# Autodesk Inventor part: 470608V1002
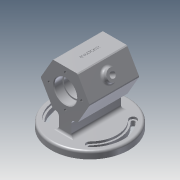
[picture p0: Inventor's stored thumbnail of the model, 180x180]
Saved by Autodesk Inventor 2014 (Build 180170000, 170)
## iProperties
Created: 2017-06
Part Number: 470608V1002
Material: 알루미늄 6061
Document SubType Name: Modeling
Designer: user
Density: 2.71 g/cm^3
Appearance: 알루미늄 - 평지
Author: user
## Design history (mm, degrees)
sketch "스케치1"
  geometry: C1 r 55 at (0, 0); 1 further point
  constraints: 1 centre point, 1 coincident
  dimensions: "d0" = 110 diameter of C1
extrude "돌출1" new body sketch "스케치1" stored distance "d1" = 10; taper "d2" = 0 deg
sketch "스케치2"
  geometry: C1 r 55 at (0, 0) reference
sketch "스케치4" dims "d4" = 60, "d10" = 46
  geometry: L1 (17.321, 87)-(34.641, 57); L2 (34.641, 57)-(17.321, 27); L3 (17.321, 27)-(-17.321, 27); L4 (-17.321, 27)-(-34.641, 57); L5 (-34.641, 57)-(-17.321, 87); L6 (-17.321, 87)-(17.321, 87); L7 (-55, -5)-(55, -5) reference; L8 (0, 110.989)-(0, -17.076); L9 (-38.809, 57)-(46.568, 57); C1 r 16 at (0, 57); 9 further points
  constraints: 16 end point, 3 coincident, 3 vertical alignment, 2 perpendicular, 1 centre point, 1 midpoint, 1 point on line, 22 other
  dimensions: "d5" = 62 distance from line of point (0, 57) L7; "d6" = 92 distance from line of L7 point (0, 87); "d11" = 32 diameter of C1; "d16" = 360 deg dimension on point (0, 57) point (0, 80) (derived)
extrude "돌출2" join sketch "스케치4" stored distance "d7" = 70; taper "d8" = 0 deg
sketch "스케치7" dims "d18" = 46
  geometry: C1 r 16 at (0, 57) reference; 6 further points
  constraints: 2 vertical alignment, 1 coincident, 7 other
  dimensions: "d21" = 360 deg dimension on C1.centre point (0, 80) (derived)
hole "구멍1" sketch "스케치7" at (0, 34), (23, 57), (-23, 57), (0, 80) diameter "d23" = 3.242; stored, may be unused: countersink angle "d27" = 90 deg, drill point angle "d29" = 118 deg; dims "d24" = 8, "d25" = 4, "d26" = 2, "d28" = 10
sketch "스케치8"
  geometry: C1 r 1.621 at (0, 34) reference; C2 r 1.621 at (23, 57) reference; C3 r 16 at (0, 57); 1 further point
  constraints: 1 centre point, 1 horizontal alignment, 1 vertical alignment
  dimensions: "d31" = 32 diameter of C3
extrude "돌출4" cut sketch "스케치8" distance "d32" = 12; taper "d33" = 0 deg
sketch "스케치9"
  geometry: C1 r 16 at (0, 0) reference; C2 r 14 at (0, 0); 1 further point
  constraints: 1 centre point, 1 coincident
  dimensions: "d34" = 28 diameter of C2
extrude "돌출5" cut sketch "스케치9" distance "d35" = 3; taper "d36" = 0 deg
sketch "스케치10"
  geometry: C1 r 14 at (0, 0) reference; C2 r 23 at (0, 0); 1 further point
  constraints: 1 centre point, 1 coincident
  dimensions: "d37" = 46 diameter of C2
extrude "돌출6" cut sketch "스케치10" stored distance "d38" = 3; taper "d39" = 0 deg
sketch "스케치14"
  geometry: L1 (-34.641, -57)-(-17.321, -87) reference; L2 (-17.321, -87)-(17.321, -87) reference; L3 (17.321, -87)-(34.641, -57) reference; L4 (34.641, -57)-(17.321, -27) reference; L5 (17.321, -27)-(-17.321, -27) reference; L6 (-17.321, -27)-(-34.641, -57) reference; C1 r 16 at (0, -57) reference; C2 r 1.621 at (-23, -57) reference; C3 r 1.621 at (0, -34) reference; C4 r 1.621 at (23, -57) reference; C5 r 1.621 at (0, -80) reference; 1 further point
sketch "스케치16"
  geometry: C1 r 8 at (-17.321, 35); C2 r 4 at (-17.321, 35); 1 further point
  constraints: 2 centre point, 1 coincident
  dimensions: "d42" = 8 diameter of C2; "d43" = 16 diameter of C1
extrude "돌출7" join sketch "스케치16" distance "d44" = 7; taper "d45" = 0 deg
extrude "돌출8" cut sketch "스케치16" distance "d46" = 7; taper "d47" = 0 deg
sketch "스케치17"
  geometry: L1 (34.641, 0)-(34.641, -70) reference; L2 (0, 0)-(34.641, 0) reference; L3 (0, -70)-(0, 0) reference; L4 (34.641, -70)-(0, -70) reference; 2 further points
  constraints: 1 coincident, 1 other
sketch "스케치18"
  geometry: L1 (0, 0)-(-77.995, 0); L2 (0, 0)-(76.146, 0); L3 (0, 0)-(0, -67.075); L4 (0, 0)-(0, 61.375); L5 (0, 0)-(-54.564, -54.564); L6 (0, 0)-(-58.275, 58.275); L7 (0, 0)-(50.976, -50.976); L8 (0, 0)-(56.326, 56.326); C1 r 55 at (0, 0) reference; C2 r 48 at (0, 0); C3 r 38 at (0, 0); A1 r 43 centre (0, 0) between (-30.406, -30.406) and (30.406, -30.406); A2 r 43 centre (0, 0) between (-30.406, 30.406) and (-30.406, -30.406); A3 r 48 centre (0, 0) between (-33.941, 33.941) and (-33.941, -33.941); A4 r 38 centre (0, 0) between (-26.87, 26.87) and (-26.87, -26.87); A5 r 5 centre (-30.406, 30.406) between (-26.87, 26.87) and (-33.941, 33.941); A6 r 5 centre (-30.406, -30.406) between (-33.941, -33.941) and (-26.87, -26.87); A7 r 43 centre (0, 0) between (30.406, -30.406) and (30.406, 30.406); A8 r 47.927 centre (0, 0) between (33.89, -33.89) and (33.89, 33.89); A9 r 38.073 centre (0, 0) between (26.922, -26.922) and (26.922, 26.922); A10 r 4.927 centre (30.406, -30.406) between (26.922, -26.922) and (33.89, -33.89); A11 r 4.927 centre (30.406, 30.406) between (33.89, 33.89) and (26.922, 26.922); A12 r 43 centre (0, 0) between (30.406, -30.406) and (30.406, 30.406); A13 r 45.5 centre (0, 0) between (32.173, -32.173) and (32.173, 32.173); A14 r 40.5 centre (0, 0) between (28.638, -28.638) and (28.638, 28.638); A15 r 2.5 centre (30.406, -30.406) between (28.638, -28.638) and (32.173, -32.173); A16 r 2.5 centre (30.406, 30.406) between (32.173, 32.173) and (28.638, 28.638); A17 r 43 centre (0, 0) between (-30.406, 30.406) and (-30.406, -30.406); A18 r 45.5 centre (0, 0) between (-32.173, 32.173) and (-32.173, -32.173); A19 r 40.5 centre (0, 0) between (-28.638, 28.638) and (-28.638, -28.638); A20 r 2.5 centre (-30.406, 30.406) between (-28.638, 28.638) and (-32.173, 32.173); A21 r 2.5 centre (-30.406, -30.406) between (-32.173, -32.173) and (-28.638, -28.638)
  constraints: 42 point on circle, 23 centre point, 16 end point, 16 tangent, 9 coincident, 3 collinear, 2 perpendicular, 2 point on line, 1 horizontal
  dimensions: "d48" = 96 diameter of C2; "d49" = 86 diameter of A1; "d50" = 76 diameter of C3; "d51" = 45 deg angle of L5 L1; "d52" = 45 deg angle of L6 L1; "d53" = 90 deg angle of L6 L5 (derived); "d54" = 45 deg angle of L2 L7 (derived); "d55" = 45 deg angle of L8 L2 (derived); "d56" = 90 deg angle of L8 L7 (derived)
extrude "돌출9" cut sketch "스케치18" distance "d59" = 3; taper "d60" = 0 deg
extrude "돌출10" cut sketch "스케치18" stored distance "d65" = 7; taper "d66" = 0 deg
sketch "스케치19"
  geometry: L1 (34.641, 57)-(17.321, 27) reference; L2 (17.321, 27)-(-17.321, 27) reference; L3 (-17.321, 27)-(-34.641, 57) reference; L4 (-34.641, 57)-(-29.981, 65.072) reference; L5 (-29.981, 65.072)-(-36.043, 68.572) reference; L6 (-36.043, 68.572)-(-34.043, 72.036) reference; L7 (-34.043, 72.036)-(-21.919, 65.036) reference; L8 (-21.919, 65.036)-(-17.919, 71.964) reference; L9 (-17.919, 71.964)-(-30.043, 78.964) reference; L10 (-30.043, 78.964)-(-28.043, 82.428) reference; L11 (-28.043, 82.428)-(-21.981, 78.928) reference; L12 (-21.981, 78.928)-(-17.321, 87) reference; L13 (-17.321, 87)-(17.321, 87) reference; L14 (17.321, 87)-(34.641, 57) reference; L15 (48, 2)-(48, 5) reference; L16 (48, 5)-(55, 5) reference; L17 (55, 5)-(55, -5) reference; L18 (55, -5)-(45.5, -5) reference; L19 (45.5, -5)-(45.5, 2) reference; L20 (45.5, 2)-(48, 2) reference; L21 (-38.073, 2)-(-38.073, 5) reference; L22 (-38.073, 5)-(38, 5) reference; L23 (38, 5)-(38, 2) reference; L24 (38, 2)-(40.5, 2) reference; L25 (40.5, 2)-(40.5, -5) reference; L26 (40.5, -5)-(-40.5, -5) reference; L27 (-40.5, -5)-(-40.5, 2) reference; L28 (-40.5, 2)-(-38.073, 2) reference; L29 (-47.927, 5)-(-47.927, 2) reference; L30 (-47.927, 2)-(-45.5, 2) reference; L31 (-45.5, 2)-(-45.5, -5) reference; L32 (-45.5, -5)-(-55, -5) reference; L33 (-55, -5)-(-55, 5) reference; L34 (-55, 5)-(-47.927, 5) reference; L35 (0, 27)-(-0.036, 5); L36 (0, 57)-(0.075, 102.246); L37 (8.837, 27)-(8.837, 5); L38 (-8.767, 27)-(-8.767, 5); C1 r 14 at (0, 57) reference; C2 r 23 at (0, 57); 1 further point
  constraints: 8 end point, 4 point on line, 2 midpoint, 2 perpendicular, 1 centre point, 1 coincident, 1 parallel
  dimensions: "d67" = 46 diameter of C2
extrude "돌출11" join sketch "스케치19" stored distance "d70" = 70; taper "d71" = 0 deg
fillet "모깎기1" dims "d72" = 5
fillet "모깎기2" dims "d73" = 5
fillet "모깎기3" dims "d74" = 3
fillet "모깎기4" dims "d75" = 3
chamfer "모따기1" distance "d76" = 1; stored, may be unused: second distance "d77" = 2, angle "d78" = 45 deg
chamfer "모따기2" distance "d79" = 1; stored, may be unused: second distance "d80" = 2, angle "d81" = 45 deg
chamfer "모따기3" distance "d82" = 1; stored, may be unused: second distance "d83" = 2, angle "d84" = 45 deg
fillet "모깎기5" dims "d85" = 3
sketch "스케치20"
  geometry: 2 further points
  constraints: 1 other
feature "엠보싱1" sketch "스케치20" dims "d4" = 60, "d5" = 62, "d6" = 92, "d10" = 46, "d11" = 32, "d16" = 360 deg (derived), "d86" = 0.5, "d87" = 0
node "솔리드1"
mirror "대칭1"
mirror "대칭2"
mirror "대칭3"
node "절단 모서리 투영1"
